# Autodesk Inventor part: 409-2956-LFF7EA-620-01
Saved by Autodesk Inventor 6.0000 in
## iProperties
Created: 2010-06
Part Number: 409-2956-LFF7EA-620-01
Cost Center: 0 lbmass
Material: A36 STEEL PLATE
Document SubType Name: Sheet Metal
Designer: S. Boerckel
Authority: 0 in^3
Mass: 7411.95 g
Surface Area: 1176.89 cm^2
Volume: 942.996 cm^3
Density: 7.86 g/cm^3
Flat Pattern Width: 17.78 cm
Flat Pattern Length: 27.94 cm
Flat Pattern Area: 496.773 cm^2
Sheet Metal Rule: 3/4"Thk
Sheet Metal Width: 11.0000 in
Sheet Metal Length: 66.0000 in^2
Description: STRAINER MOUNT PLATE
User Status: BURN
SaveDate: 2008-01-15
SaveTime: 10:24
FileName: Sheet Metal
Wide: =<Flat Pattern Width>cm
Length: =<Flat Pattern Length>cm
Thickness: 0.7500 in
SMR: =<Sheet Metal Rule> - <Material>
Author: S. Boerckel
Revision Number: A
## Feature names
1. Hole1
2. Plate1
